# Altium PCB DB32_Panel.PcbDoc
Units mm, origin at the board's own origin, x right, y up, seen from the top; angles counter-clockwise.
Board outline 256.4 x 198.8 mm, 8 copper layers (Top Layer, MidLayer1, MidLayer2, GND-Layer5, MidLayer3, 3V3, MidLayer4, Bottom Layer), stack 1.318 mm thick; 0 components, 444 nets, 12 pads, 0 vias.
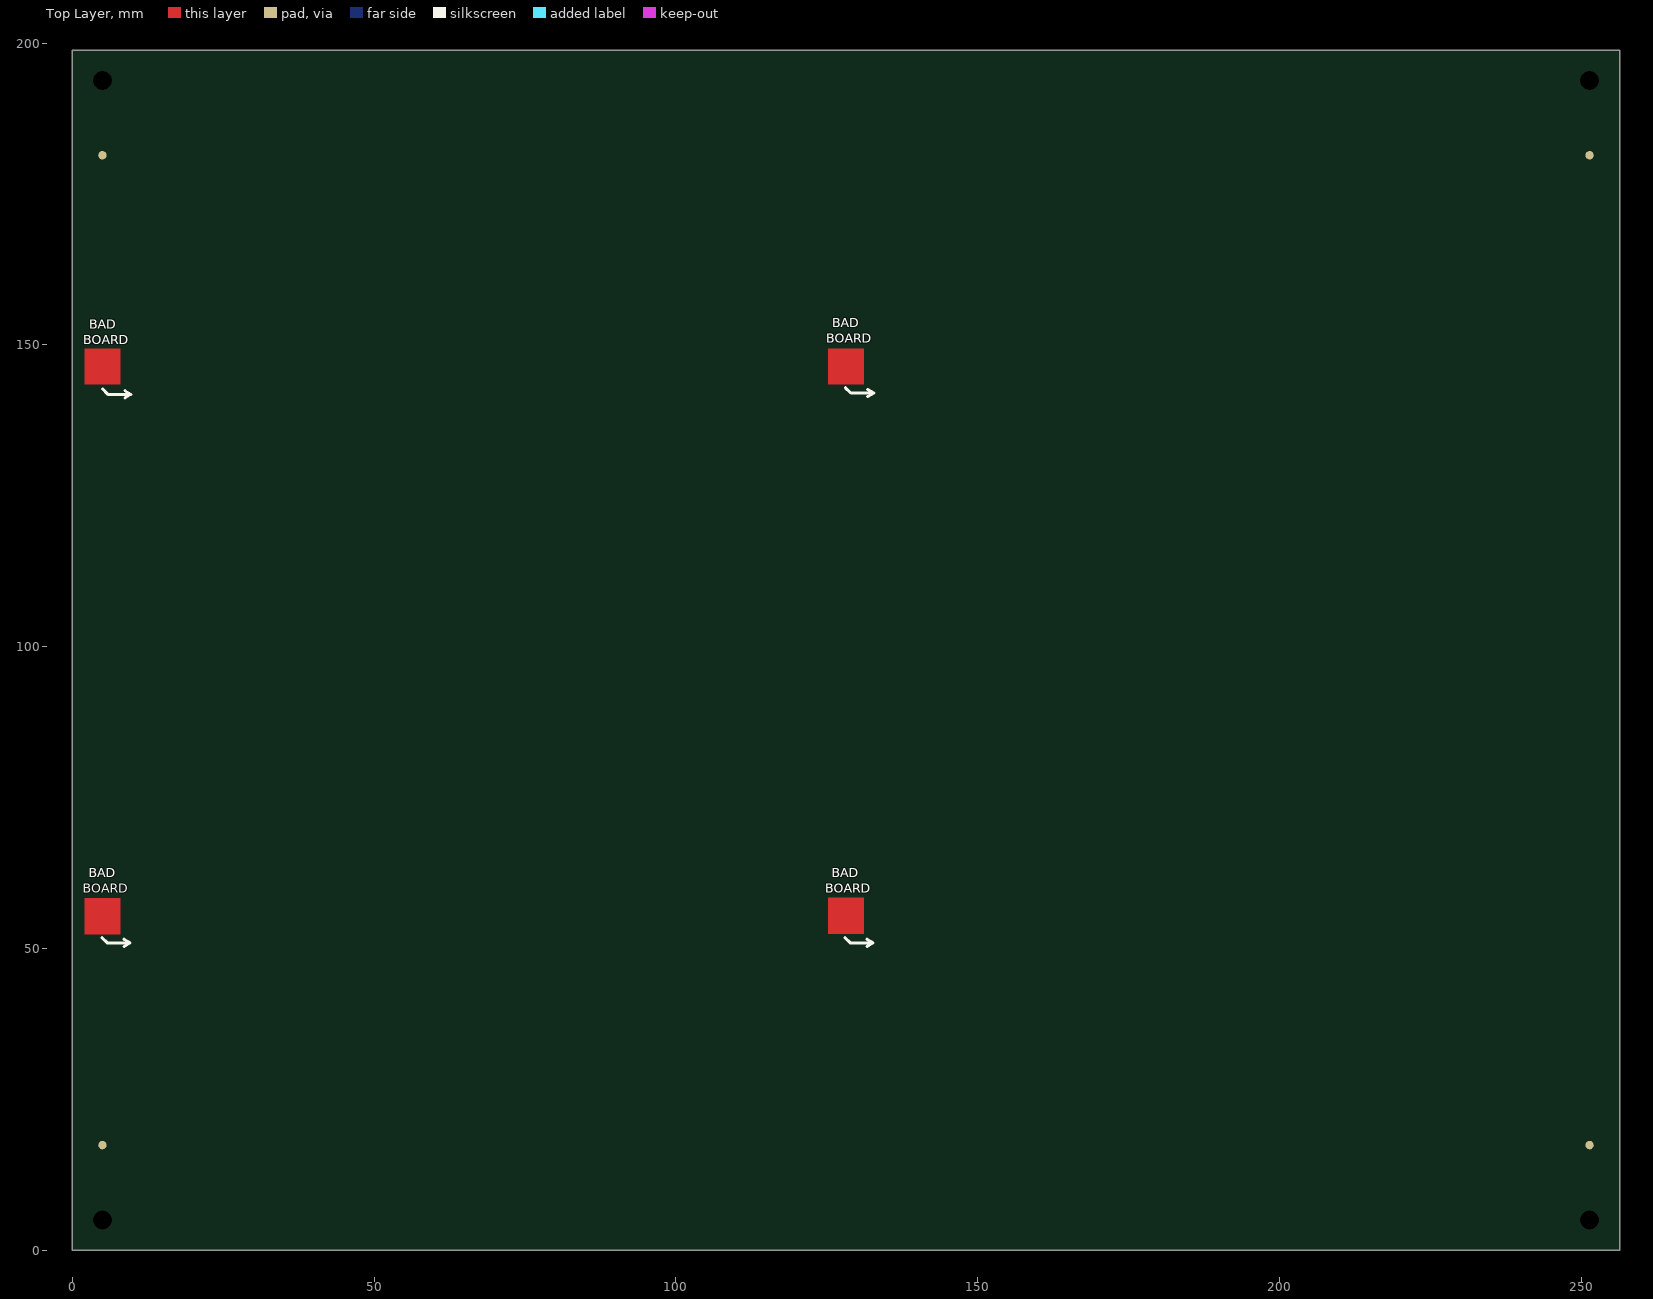
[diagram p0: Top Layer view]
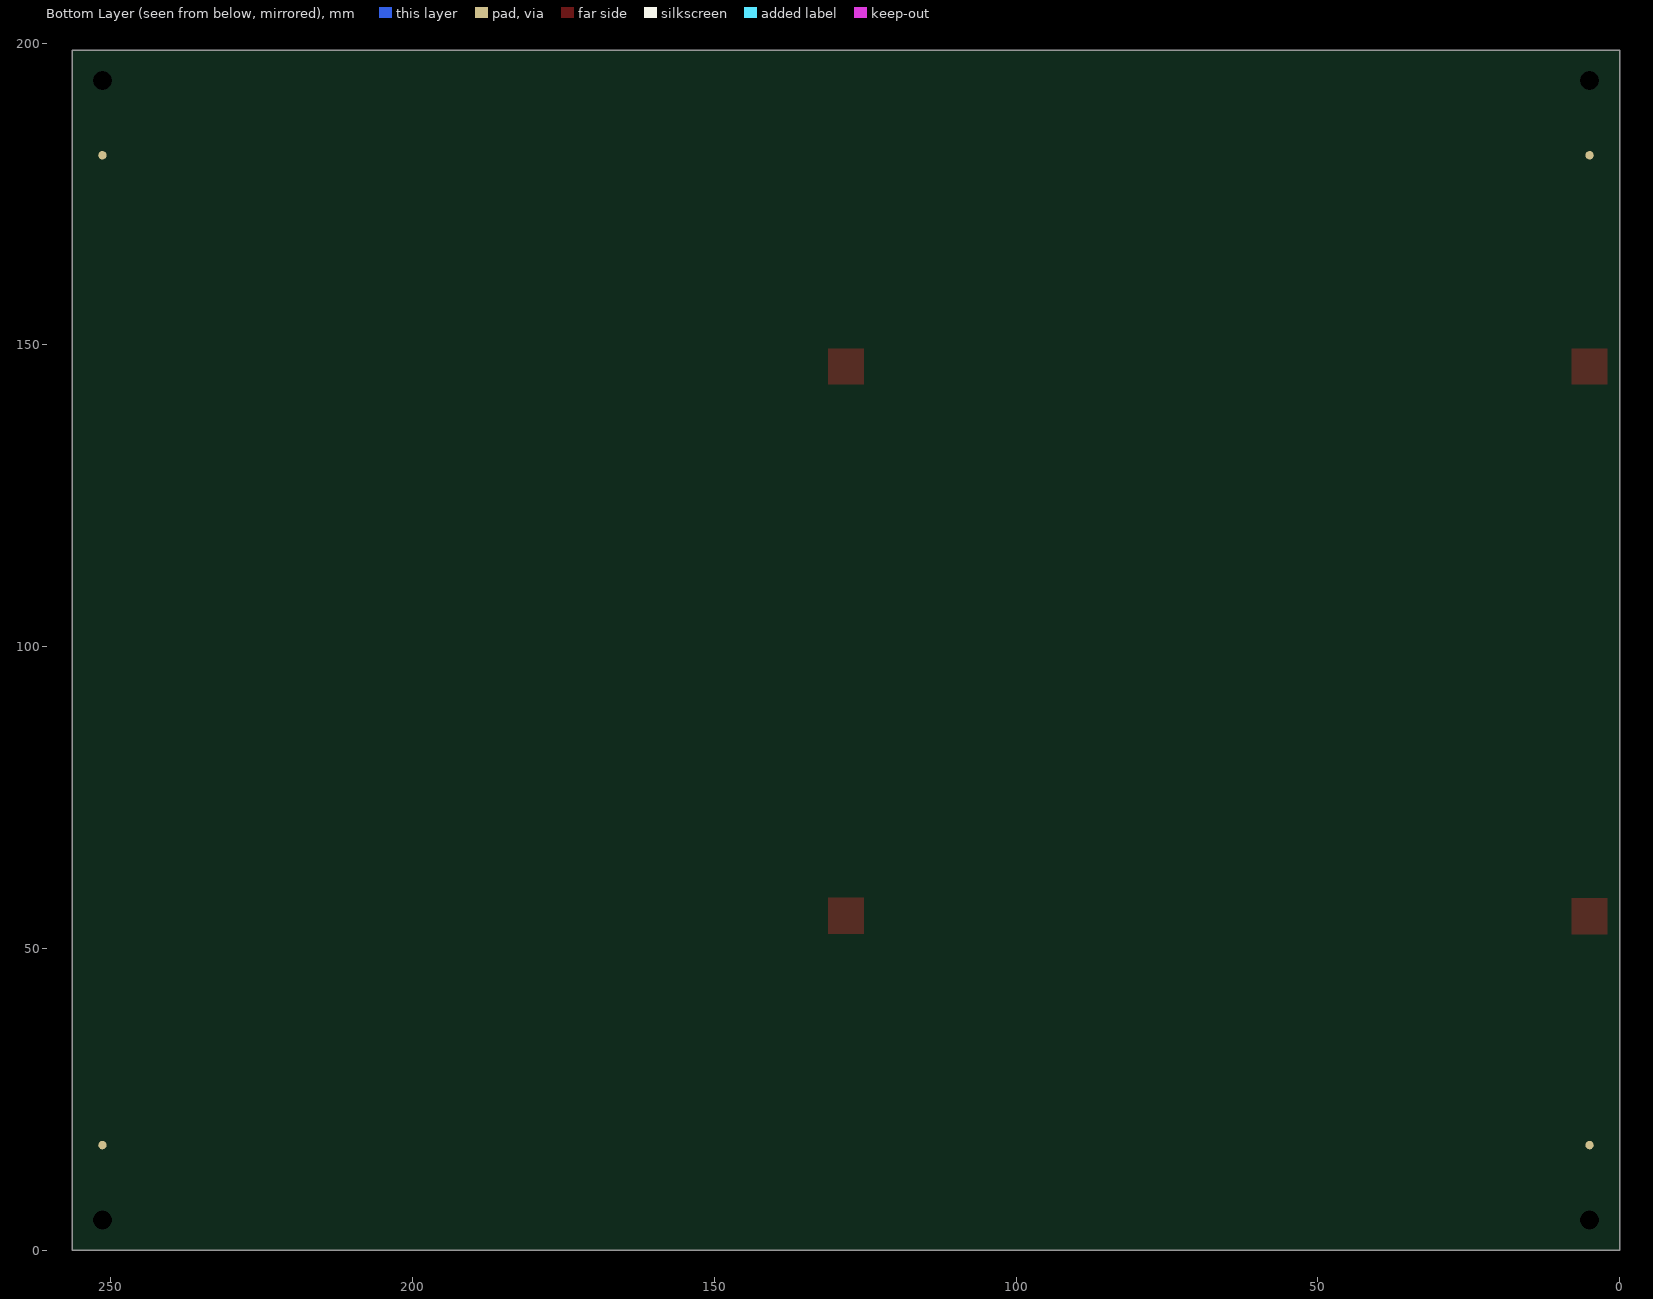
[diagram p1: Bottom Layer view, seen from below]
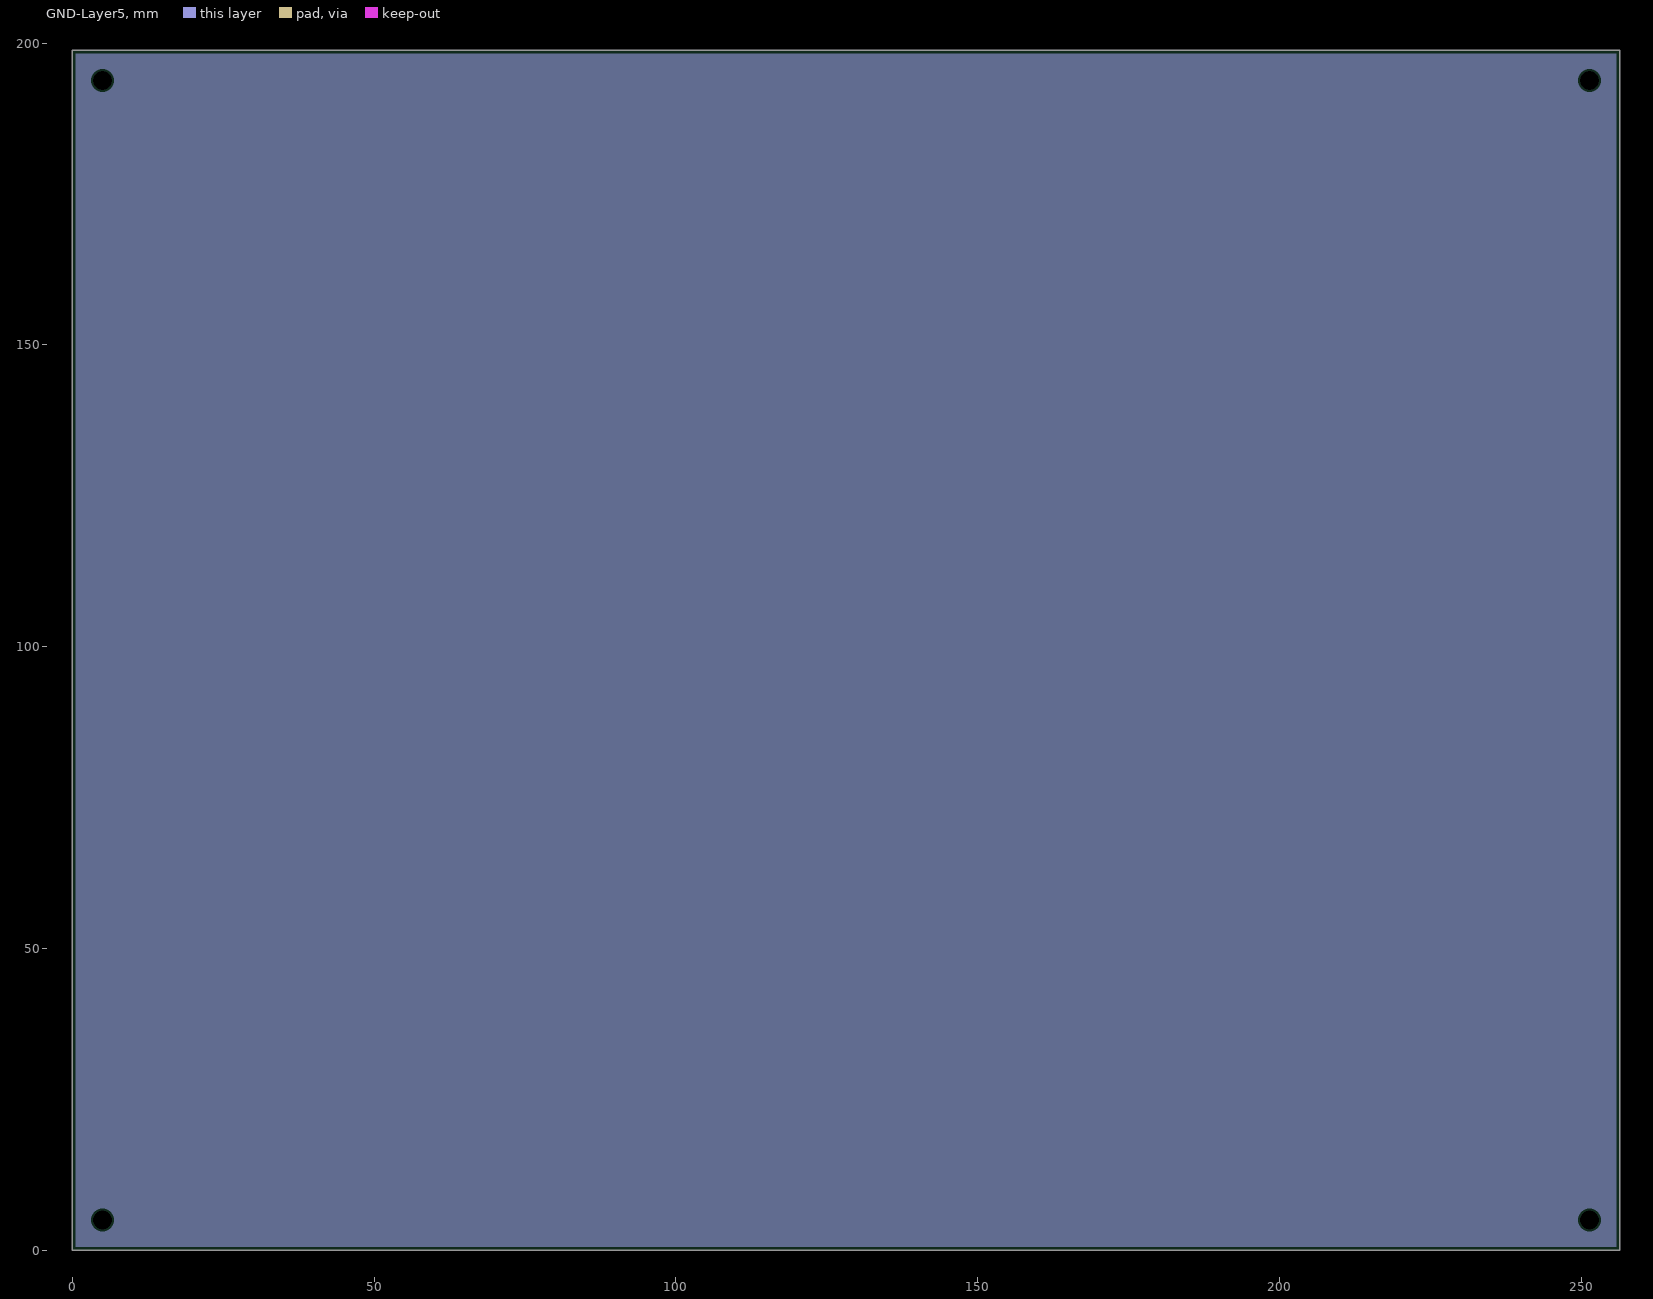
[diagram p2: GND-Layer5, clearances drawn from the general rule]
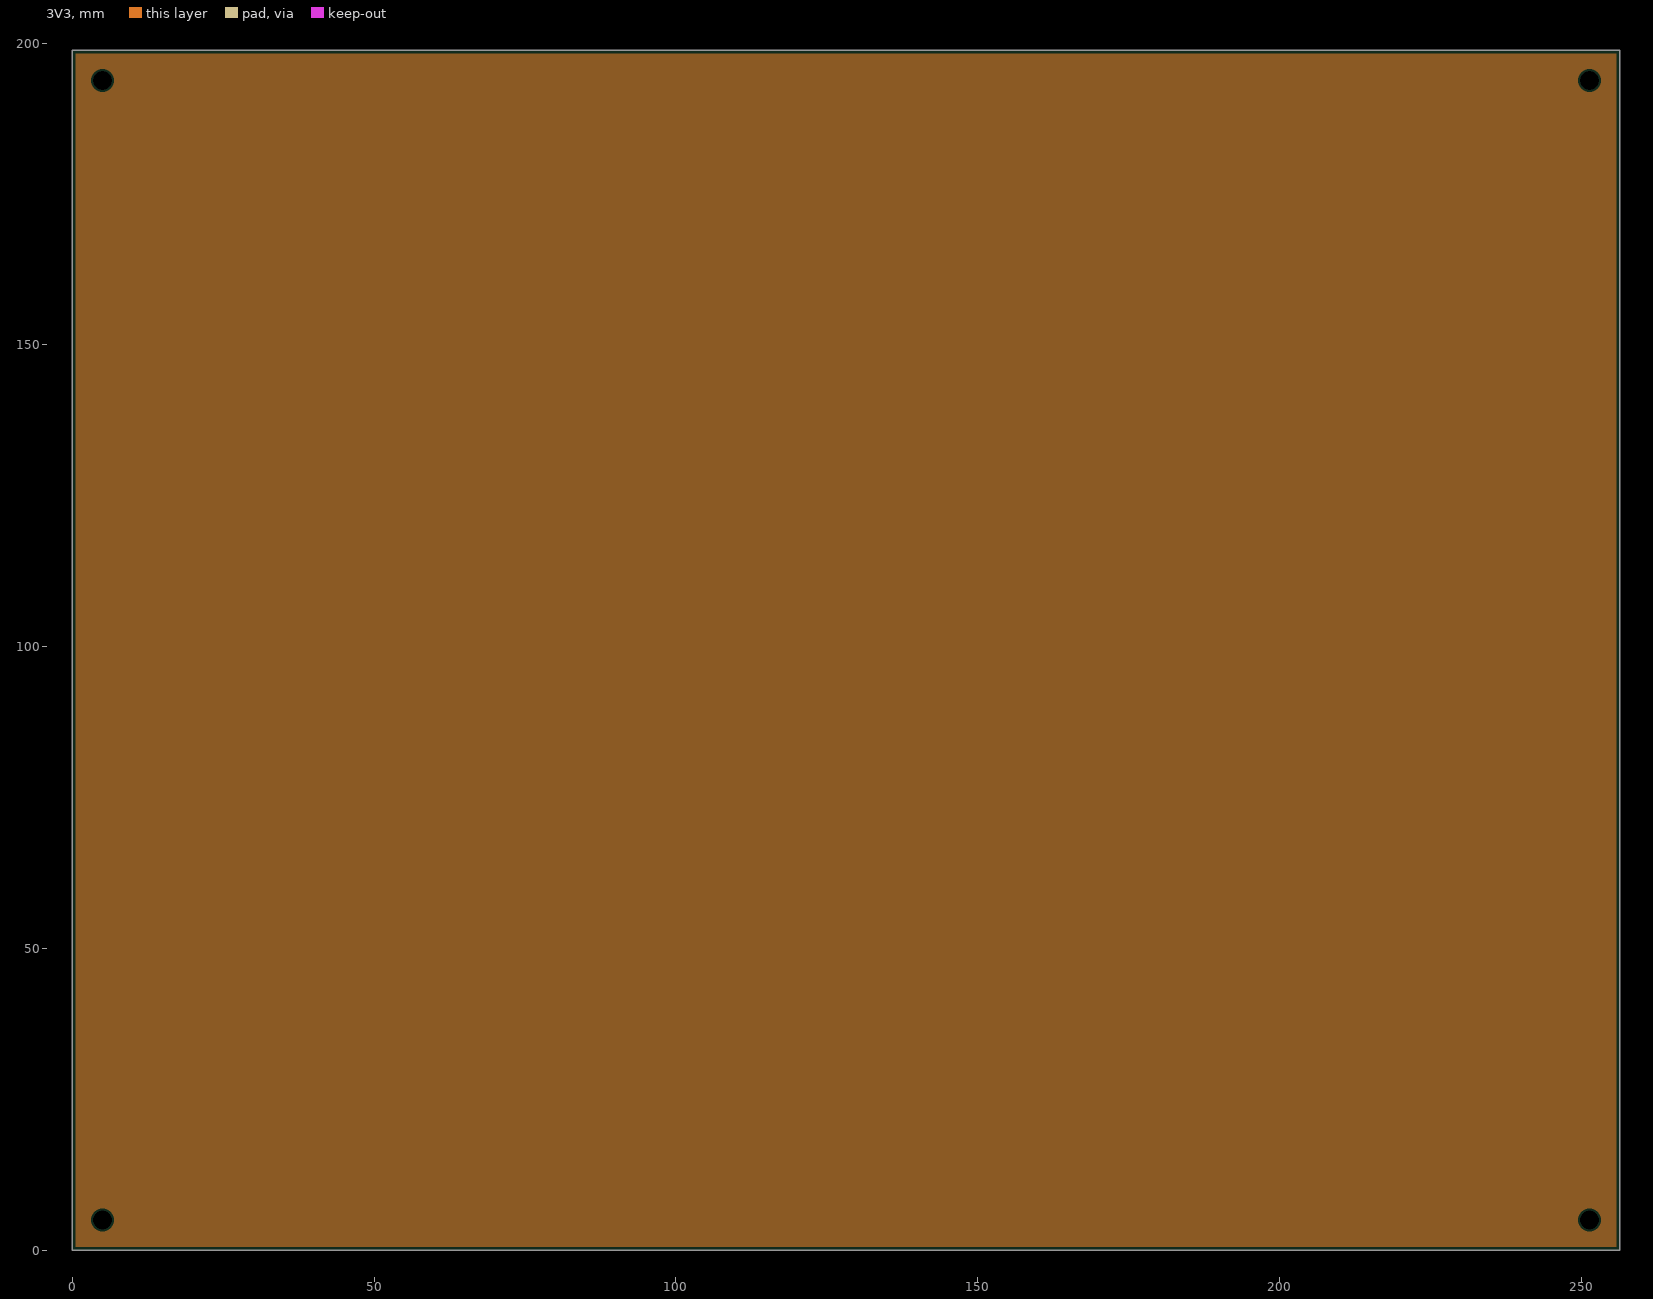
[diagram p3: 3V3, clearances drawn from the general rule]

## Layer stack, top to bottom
Top Layer: signal copper 0.043
Dielectric: prepreg 0.076, FR-4, Dk 4.3
MidLayer1: signal copper 0.0356
Dielectric: core 0.229, FR-4, Dk 4.8
MidLayer2: signal copper 0.0356
Dielectric: prepreg 0.102, FR-4, Dk 4.3
GND-Layer5: plane copper 0.036, net GND
Dielectric: core 0.178, FR-4, Dk 4.8
MidLayer3: signal copper 0.0356
Dielectric: prepreg 0.102, FR-4, Dk 4.8
3V3: plane copper 0.036, net 3V3
Dielectric: core 0.229, FR-4, Dk 4.8
MidLayer4: signal copper 0.0356
Dielectric: prepreg 0.102, FR-4, Dk 4.8
Bottom Layer: signal copper 0.043

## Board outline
0,0 0,198.8 256.3,198.8 256.4,198.8 256.4,0

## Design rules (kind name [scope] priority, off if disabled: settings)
Clearance Clearance_Poly_Tight [InNamedPolygon('FPGAPWR-TL-1V2') Or InNamedPolygon('FPGAPWR-BL-1V2') Or InNamedPolygon('FPGAPWR-BL-3V3') Or InNamedPolygon('FPGAPWR-BL-2V5A') Or InNamedPolygon('FPGAPWR-BL-2V5B') Or InNamedPolygon('FPGAPWR-BL-2V5C') Or InNamedPolygon('FPGAPWR-BL-2V5D') Or InNamedPolygon('FPGAPWR-ML1-1V2') Or InNamedPolygon('FPGAPWR-BL-2V5E') Or InNamedPolygon('FPGAPWR-BL-3V3' )] p1: gap=0.127
Clearance Clearance_Polygon [InPolygon] p2: gap=0.2
Clearance "Pad-Pad Clearance Same Net" [IsPad vs IsPad] p3: gap=0.127
Clearance "Via-Pad Clearance" [IsVia vs IsPad] p4: gap=0.1
Clearance "General Clearance" [All] p5: gap=0.127
ComponentClearance [All] p1 off: gap=0.2 collisioncheckmode=3 verticalgap=0.254 showdistances=FALSE
DiffPairsRouting [All] p1: maxlimit=0.127 minlimit=0.127 mostfreqgap=0.127 maxuncoupledlength=5.08
FabricationTestPointUsage TestPointUsage [All] p1 off: valid=0 allowmultiple=FALSE
FabricationTestpoint Testpoint [All] p1 off: side=3 testpointundercomponent=TRUE minsize=1.016 maxsize=2.54 preferedsize=1.524 minholesize=0 maxholesize=1.016 preferedholesize=0.813 testpointgrid=0.025 allowsidetop=TRUE allowsidebottom=TRUE usegrid=TRUE gridtolerance=0
HoleSize [All] p1: absolutevalues=TRUE maxlimit=5.2 minlimit=0.2 maxpercent=80.000 minpercent=20.000
MatchedLengths DiffPair_MatchedLengths [(IsDifferentialPair And (Name = 'DIFF_RX1'))] p1: tolerance=25.4 checknetsindiffpair=TRUE checkdiffpairvsdiffpair=TRUE checkothers=TRUE
MinimumAnnularRing MinimumAnnularRing_NonPlated [(ObjectKind = 'Pad') And (HoleDiameter >= '0.7') And (PadIsPlated = 'False')] p1: minimumring=-5
MinimumAnnularRing [All] p2: minimumring=0.15
PlaneClearance [All] p1: clearance=0.3
PlaneConnect [All] p1: planeconnectstyle=Direct reliefexpansion=0.5 reliefentries=4 reliefconductorwidth=0.25 reliefairgap=0.25
PolygonConnect PolygonConnect_Via [IsVia] p1: connectstyle=Direct reliefconductorwidth=0.254 reliefentries=4 polygonreliefangle="90 Angle"
PolygonConnect "PolygonConnect - Heatsink" [(HasFootprint('TO-263') AND InNet('VCCINT'))] p2: connectstyle=Direct reliefconductorwidth=0.254 reliefentries=4 polygonreliefangle="90 Angle"
PolygonConnect [All] p3: connectstyle=Relief reliefconductorwidth=0.3 reliefentries=4 polygonreliefangle="90 Angle"
RoutingLayers [All] p1: top layer_v5=FALSE mid layer 1_v5=FALSE mid layer 2_v5=FALSE mid layer 3_v5=FALSE mid layer 4_v5=FALSE bottom layer_v5=FALSE
RoutingVias [All] p1: holewidth=0.3 width=0.6 viastyle="Through Hole" minholewidth=0.3 minwidth=0.6 maxholewidth=0.5 maxwidth=0.9
ShortCircuit ShortCircuit_1 [Net = 'No Net' vs Net = 'No Net'] p1: allowed=TRUE
ShortCircuit [All] p2: allowed=FALSE
SilkscreenOverComponentPads [All] p1: minsilkscreentomaskgap=0.254
SolderMaskExpansion SolderMaskExpansion_Vias [IsVia] p1: expansion=-0.65
SolderMaskExpansion [All] p2: expansion=0.1
Width [All] p1: maxlimit=2.5 minlimit=0.127 preferedwidth=0.127
18 further rules are at their usual default settings.

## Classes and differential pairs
component class MOUNTS-PCB: MH1 MH2 MH3
component class DaughterBoard_FPGA: MH1 MH2 MH3
net class PLL: VCCA_PLL1 VCCA_PLL2 VCCA_PLL3 VCCA_PLL4
net class FPGACONF: CONF_DONE DATA0 DCLK FPGA_CCLK FPGA_DIN FPGA_DONE FPGA_INIT FPGA_M0 FPGA_M1 FPGA_PROGRAM FPGA_TCK FPGA_TDI FPGA_TDO FPGA_TMS MSEL0 MSEL1 NCONFIG NSTATUS TCK TDI TDO TMS
component class U_Bypass_1V2: C1_FP C2_FP C3_FP C4_FP C5_FP C6_FP C7_FP C8_FP C9_FP C10_FP C11_FP C12_FP C13_FP C14_FP C15_FP C16_FP C17_FP C18_FP C19_FP C20_FP C21_FP C22_FP C23_FP C24_FP C25_FP C26_FP C27_FP C28_FP C29_FP C30_FP C31_FP
component class COMP_PLL: C1_PL C2_PL C3_PL C4_PL C5_PL C6_PL C7_PL C8_PL C9_PL C10_PL C11_PL C12_PL C13_PL C14_PL C15_PL C16_PL L2 L3 L4 L5
component class COMP_1V2: C15 C17 C18 C19 C20 C21 C22 L1_PS NT1 NT7 R13 R17
component class U_FPGA_Power: C1_PL C2_PL C3_PL C4_PL C5_PL C6_PL C7_PL C8_PL C9_PL C10_PL C11_PL C12_PL C13_PL C14_PL C15_PL C16_PL L2 L3 L4 L5
net class PWRNET: 1V2 3V3 5V0 AGND GND
differential pair class DIFF_OUT: DIFF_TX0 DIFF_TX1 DIFF_TX2 DIFF_TX3
differential pair class DIFF_IN: DIFF_RX0 DIFF_RX1 DIFF_RX2 DIFF_RX3
net class SW[4..0]: SW0 SW1 SW2 SW3 SW4
net class SRAM_NBE[3..0]: SRAM_NBE0 SRAM_NBE1 SRAM_NBE2 SRAM_NBE3
net class SRAM_D[31..0]: SRAM_D0 SRAM_D1 SRAM_D2 SRAM_D3 SRAM_D4 SRAM_D5 SRAM_D6 SRAM_D7 SRAM_D8 SRAM_D9 SRAM_D10 SRAM_D11 SRAM_D12 SRAM_D13 SRAM_D14 SRAM_D15 SRAM_D16 SRAM_D17 SRAM_D18 SRAM_D19 SRAM_D20 SRAM_D21 SRAM_D22 SRAM_D23 SRAM_D24 SRAM_D25 SRAM_D26 SRAM_D27 SRAM_D28 SRAM_D29 SRAM_D30 SRAM_D31
net class LED[7..0]: LED0 LED1 LED2 LED3 LED4 LED5 LED6 LED7
net class IO[35..0]: IO0 IO1 IO2 IO3 IO4 IO5 IO6 IO7 IO8 IO9 IO10 IO11 IO12 IO13 IO14 IO15 IO16 IO17 IO18 IO19 IO20 IO21 IO22 IO23 IO24 IO25 IO26 IO27 IO28 IO29 IO30 IO31 IO32 IO33 IO34 IO35
net class FPGA_M[2..0]: FPGA_M0 FPGA_M1 FPGA_M2
net class FPGA_ID[3..0]: FPGA_ID0 FPGA_ID1 FPGA_ID2 FPGA_ID3
net class DIP[7..0]: DIP0 DIP1 DIP2 DIP3 DIP4 DIP5 DIP6 DIP7
net class BUS_NBE[3..0]: BUS_NBE0 BUS_NBE1 BUS_NBE2 BUS_NBE3
net class BUS_D[31..0]: BUS_D0 BUS_D1 BUS_D2 BUS_D3 BUS_D4 BUS_D5 BUS_D6 BUS_D7 BUS_D8 BUS_D9 BUS_D10 BUS_D11 BUS_D12 BUS_D13 BUS_D14 BUS_D15 BUS_D16 BUS_D17 BUS_D18 BUS_D19 BUS_D20 BUS_D21 BUS_D22 BUS_D23 BUS_D24 BUS_D25 BUS_D26 BUS_D27 BUS_D28 BUS_D29 BUS_D30 BUS_D31
component class U_SPARTAN3: NT2 NT3 NT4 NT5 NT6 NT8 R1 R2 R3 R4 R7 R8 R12 R14 R18 R20 R22 R23 R24 R25 R26 R27 U1
component class U_LEDS: C98 LED1 LED2 R19 R21 U9
component class U_MotherBoardConnectors: HDR_B HDR_L HDR_T NT1
component class U_SRAM_Free: C1_M C2_M C2B C3_M C4_M C4B C5_M C5B C6_M C7_M C7B C8_M C8B C9_M C9B C10_M C10B C12_M C12B U7B U8B U18 U20
component class U_Bypass_3V3: C38_FP C39_FP C40_FP C41_FP C42_FP C43_FP C44_FP C45_FP C46_FP C47_FP C48_FP C49_FP C50_FP C51_FP C52_FP C53_FP C54_FP C55_FP C56_FP C57_FP C58_FP C59_FP C60_FP C61_FP C62_FP C63_FP C64_FP C65_FP C66_FP C67_FP C68_FP C69_FP C70_FP C71_FP C72_FP C73_FP C74_FP C75_FP C76_FP C77_FP C78_FP C79_FP C80_FP C81_FP C82_FP C83_FP C84_FP C85_FP C86_FP C87_FP C88_FP C89_FP C90_FP C91_FP C92_FP C93_FP C94_FP C95_FP C96_FP C97_FP C98_FP C99_FP C100_FP C101_FP C102_FP C103_FP C104_FP C105_FP C106_FP
component class U_Bypass_Board: C1_MB C1_PSU C2_MB C3_MB C4_MB C6_MB
component class U_FLASH: C1_CM C2_CM C3_CM C4_CM C5_CM C6_CM U1_CM
component class U_SDRAM: C7_CM C8_CM C9_CM C10_CM C11_CM C12_CM C13_CM C14_CM U2_CM U3_CM
component class U_SRAM_Common: C15_CM C16_CM C17_CM C18_CM C19_CM C20_CM C21_CM C22_CM U4_CM U5_CM
net class BUS_A[24..1]: BUS_A1 BUS_A2 BUS_A3 BUS_A4 BUS_A5 BUS_A6 BUS_A7 BUS_A8 BUS_A9 BUS_A10 BUS_A11 BUS_A12 BUS_A13 BUS_A14 BUS_A15 BUS_A16 BUS_A17 BUS_A18 BUS_A19 BUS_A20 BUS_A21 BUS_A22 BUS_A23 BUS_A24
net class DAU_TFT_BLUE[4..0]: DAU_TFT_BLUE0 DAU_TFT_BLUE1 DAU_TFT_BLUE2 DAU_TFT_BLUE3 DAU_TFT_BLUE4
net class DAU_TFT_CL[3..1]: DAU_TFT_CL1 DAU_TFT_CL2 DAU_TFT_CL3
net class DAU_TFT_GREEN[5..0]: DAU_TFT_GREEN0 DAU_TFT_GREEN1 DAU_TFT_GREEN2 DAU_TFT_GREEN3 DAU_TFT_GREEN4 DAU_TFT_GREEN5
net class DAU_TFT_RED[4..0]: DAU_TFT_RED0 DAU_TFT_RED1 DAU_TFT_RED2 DAU_TFT_RED3 DAU_TFT_RED4
net class EXTEND_A[49..0]: EXTEND_A0 EXTEND_A1 EXTEND_A2 EXTEND_A3 EXTEND_A4 EXTEND_A5 EXTEND_A6 EXTEND_A7 EXTEND_A8 EXTEND_A9 EXTEND_A10 EXTEND_A11 EXTEND_A12 EXTEND_A13 EXTEND_A14 EXTEND_A15 EXTEND_A16 EXTEND_A17 EXTEND_A18 EXTEND_A19 EXTEND_A20 EXTEND_A21 EXTEND_A22 EXTEND_A23 EXTEND_A24 EXTEND_A25 EXTEND_A26 EXTEND_A27 EXTEND_A28 EXTEND_A29 EXTEND_A30 EXTEND_A31 EXTEND_A32 EXTEND_A33 EXTEND_A34 EXTEND_A35 EXTEND_A36 EXTEND_A37 EXTEND_A38 EXTEND_A39 EXTEND_A40 EXTEND_A41 EXTEND_A42 EXTEND_A43 EXTEND_A44 EXTEND_A45 EXTEND_A46 EXTEND_A47 EXTEND_A48 EXTEND_A49
net class EXTEND_B[49..0]: EXTEND_B0 EXTEND_B1 EXTEND_B2 EXTEND_B3 EXTEND_B4 EXTEND_B5 EXTEND_B6 EXTEND_B7 EXTEND_B8 EXTEND_B9 EXTEND_B10 EXTEND_B11 EXTEND_B12 EXTEND_B13 EXTEND_B14 EXTEND_B15 EXTEND_B16 EXTEND_B17 EXTEND_B18 EXTEND_B19 EXTEND_B20 EXTEND_B21 EXTEND_B22 EXTEND_B23 EXTEND_B24 EXTEND_B25 EXTEND_B26 EXTEND_B27 EXTEND_B28 EXTEND_B29 EXTEND_B30 EXTEND_B31 EXTEND_B32 EXTEND_B33 EXTEND_B34 EXTEND_B35 EXTEND_B36 EXTEND_B37 EXTEND_B38 EXTEND_B39 EXTEND_B40 EXTEND_B41 EXTEND_B42 EXTEND_B43 EXTEND_B44 EXTEND_B45 EXTEND_B46 EXTEND_B47 EXTEND_B48 EXTEND_B49
net class EXTEND_C[49..0]: EXTEND_C0 EXTEND_C1 EXTEND_C2 EXTEND_C3 EXTEND_C4 EXTEND_C5 EXTEND_C6 EXTEND_C7 EXTEND_C8 EXTEND_C9 EXTEND_C10 EXTEND_C11 EXTEND_C12 EXTEND_C13 EXTEND_C14 EXTEND_C15 EXTEND_C16 EXTEND_C17 EXTEND_C18 EXTEND_C19 EXTEND_C20 EXTEND_C21 EXTEND_C22 EXTEND_C23 EXTEND_C24 EXTEND_C25 EXTEND_C26 EXTEND_C27 EXTEND_C28 EXTEND_C29 EXTEND_C30 EXTEND_C31 EXTEND_C32 EXTEND_C33 EXTEND_C34 EXTEND_C35 EXTEND_C36 EXTEND_C37 EXTEND_C38 EXTEND_C39 EXTEND_C40 EXTEND_C41 EXTEND_C42 EXTEND_C43 EXTEND_C44 EXTEND_C45 EXTEND_C46 EXTEND_C47 EXTEND_C48 EXTEND_C49
net class SRAM_A[20..0]: SRAM_A0 SRAM_A1 SRAM_A2 SRAM_A3 SRAM_A4 SRAM_A5 SRAM_A6 SRAM_A7 SRAM_A8 SRAM_A9 SRAM_A10 SRAM_A11 SRAM_A12 SRAM_A13 SRAM_A14 SRAM_A15 SRAM_A16 SRAM_A17 SRAM_A18
component class U_Memory_CommonBus: C23_CM C24_CM
component class U_PSU_MAX1831_1V2: C15 C16 C17 C18 C19 C20 C21 C22 L1_PS R11 R13 R15 R16 R17 TP7 TP8 U2
component class U_PSU: NT7 R5 R6 TP1 TP2 TP3 TP4

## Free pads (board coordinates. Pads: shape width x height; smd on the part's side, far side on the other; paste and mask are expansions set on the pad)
  round 2.692 hole 3.2 unplated mask+0.889: 126N(5,5) 126N(5,193.8) 126N(251.4,5) 126N(251.4,193.8)
  round 1.397 smd far side paste-2.54 mask+1.321: fidbot(5,17.4) fidbot(5,181.4) fidbot(251.4,17.4) fidbot(251.4,181.4)
  round 1.397 smd paste-2.54 mask+1.321: fidtop(5,17.4) fidtop(5,181.4) fidtop(251.4,17.4) fidtop(251.4,181.4)

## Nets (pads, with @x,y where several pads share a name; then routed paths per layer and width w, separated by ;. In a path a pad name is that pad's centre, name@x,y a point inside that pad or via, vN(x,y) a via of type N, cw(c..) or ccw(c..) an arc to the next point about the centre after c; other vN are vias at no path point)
1V2: 
3V3: 
5V0: 
AGND: 
BUS_A1: 
BUS_A2: 
BUS_A3: 
BUS_A4: 
BUS_A5: 
BUS_A6: 
BUS_A7: 
BUS_A8: 
BUS_A9: 
BUS_A10: 
BUS_A11: 
BUS_A12: 
BUS_A13: 
BUS_A14: 
BUS_A15: 
BUS_A16: 
BUS_A17: 
BUS_A18: 
BUS_A19: 
BUS_A20: 
BUS_A21: 
BUS_A22: 
BUS_A23: 
BUS_A24: 
BUS_D0: 
BUS_D1: 
BUS_D2: 
BUS_D3: 
BUS_D4: 
BUS_D5: 
BUS_D6: 
BUS_D7: 
BUS_D8: 
BUS_D9: 
BUS_D10: 
BUS_D11: 
BUS_D12: 
BUS_D13: 
BUS_D14: 
BUS_D15: 
BUS_D16: 
BUS_D17: 
BUS_D18: 
BUS_D19: 
BUS_D20: 
BUS_D21: 
BUS_D22: 
BUS_D23: 
BUS_D24: 
BUS_D25: 
BUS_D26: 
BUS_D27: 
BUS_D28: 
BUS_D29: 
BUS_D30: 
BUS_D31: 
BUS_FLASH_NBUSY: 
BUS_FLASH_NCS: 
BUS_FLASH_NRESET: 
BUS_NBE0: 
BUS_NBE1: 
BUS_NBE2: 
BUS_NBE3: 
BUS_NOE: 
BUS_NWE: 
BUS_RAM_NCS: 
BUS_SDRAM_CKE: 
BUS_SDRAM_CLK: 
BUS_SDRAM_NCAS: 
BUS_SDRAM_NCS: 
BUS_SDRAM_NRAS: 
BUZZER: 
CAN_RXD: 
CAN_TXD: 
COMP: 
CONF_DONE: 
DATA0: 
DAU_RESET_SW: 
DAU_SPARE: 
DAU_TFT_BLIGHT: 
DAU_TFT_BLUE0: 
DAU_TFT_BLUE1: 
DAU_TFT_BLUE2: 
DAU_TFT_BLUE3: 
DAU_TFT_BLUE4: 
DAU_TFT_CL1: 
DAU_TFT_CL2: 
DAU_TFT_CL3: 
DAU_TFT_DISP_ON: 
DAU_TFT_GREEN0: 
DAU_TFT_GREEN1: 
DAU_TFT_GREEN2: 
DAU_TFT_GREEN3: 
DAU_TFT_GREEN4: 
DAU_TFT_GREEN5: 
DAU_TFT_IRQ: 
DAU_TFT_M: 
DAU_TFT_MUX: 
DAU_TFT_POL: 
DAU_TFT_RED0: 
DAU_TFT_RED1: 
DAU_TFT_RED2: 
DAU_TFT_RED3: 
DAU_TFT_RED4: 
DAU_TFT_STH: 
DAU_TFT_STV: 
DCLK: 
DIP0: 
DIP1: 
DIP2: 
DIP3: 
DIP4: 
DIP5: 
DIP6: 
DIP7: 
EXTEND_A0: 
EXTEND_A1: 
EXTEND_A2: 
EXTEND_A3: 
EXTEND_A4: 
EXTEND_A5: 
EXTEND_A6: 
EXTEND_A7: 
EXTEND_A8: 
EXTEND_A9: 
EXTEND_A10: 
EXTEND_A11: 
EXTEND_A12: 
EXTEND_A13: 
EXTEND_A14: 
EXTEND_A15: 
EXTEND_A16: 
EXTEND_A17: 
EXTEND_A18: 
EXTEND_A19: 
EXTEND_A20: 
EXTEND_A21: 
EXTEND_A22: 
EXTEND_A23: 
EXTEND_A24: 
EXTEND_A25: 
EXTEND_A26: 
EXTEND_A27: 
EXTEND_A28: 
EXTEND_A29: 
EXTEND_A30: 
EXTEND_A31: 
EXTEND_A32: 
EXTEND_A33: 
EXTEND_A34: 
EXTEND_A35: 
EXTEND_A36: 
EXTEND_A37: 
EXTEND_A38: 
EXTEND_A39: 
EXTEND_A40: 
EXTEND_A41: 
EXTEND_A42: 
EXTEND_A43: 
EXTEND_A44: 
EXTEND_A45: 
EXTEND_A46: 
EXTEND_A47: 
EXTEND_A48: 
EXTEND_A49: 
EXTEND_B0: 
EXTEND_B1: 
EXTEND_B2: 
EXTEND_B3: 
EXTEND_B4: 
EXTEND_B5: 
EXTEND_B6: 
EXTEND_B7: 
EXTEND_B8: 
EXTEND_B9: 
EXTEND_B10: 
EXTEND_B11: 
EXTEND_B12: 
EXTEND_B13: 
EXTEND_B14: 
EXTEND_B15: 
EXTEND_B16: 
EXTEND_B17: 
EXTEND_B18: 
EXTEND_B19: 
EXTEND_B20: 
EXTEND_B21: 
EXTEND_B22: 
EXTEND_B23: 
EXTEND_B24: 
EXTEND_B25: 
EXTEND_B26: 
EXTEND_B27: 
EXTEND_B28: 
EXTEND_B29: 
EXTEND_B30: 
EXTEND_B31: 
EXTEND_B32: 
EXTEND_B33: 
EXTEND_B34: 
EXTEND_B35: 
EXTEND_B36: 
EXTEND_B37: 
EXTEND_B38: 
EXTEND_B39: 
EXTEND_B40: 
EXTEND_B41: 
EXTEND_B42: 
EXTEND_B43: 
EXTEND_B44: 
EXTEND_B45: 
EXTEND_B46: 
EXTEND_B47: 
EXTEND_B48: 
EXTEND_B49: 
EXTEND_C0: 
EXTEND_C1: 
EXTEND_C2: 
EXTEND_C3: 
EXTEND_C4: 
EXTEND_C5: 
EXTEND_C6: 
EXTEND_C7: 
EXTEND_C8: 
EXTEND_C9: 
EXTEND_C10: 
EXTEND_C11: 
EXTEND_C12: 
EXTEND_C13: 
EXTEND_C14: 
EXTEND_C15: 
EXTEND_C16: 
EXTEND_C17: 
EXTEND_C18: 
EXTEND_C19: 
EXTEND_C20: 
EXTEND_C21: 
EXTEND_C22: 
EXTEND_C23: 
EXTEND_C24: 
EXTEND_C25: 
EXTEND_C26: 
EXTEND_C27: 
EXTEND_C28: 
EXTEND_C29: 
EXTEND_C30: 
EXTEND_C31: 
EXTEND_C32: 
EXTEND_C33: 
EXTEND_C34: 
EXTEND_C35: 
EXTEND_C36: 
EXTEND_C37: 
EXTEND_C38: 
EXTEND_C39: 
EXTEND_C40: 
EXTEND_C41: 
EXTEND_C42: 
EXTEND_C43: 
EXTEND_C44: 
EXTEND_C45: 
EXTEND_C46: 
EXTEND_C47: 
EXTEND_C48: 
EXTEND_C49: 
FB: 
FPGA_CCLK: 
FPGA_CLK: 
FPGA_CLK1: 
FPGA_CLK2: 
FPGA_DIN: 
FPGA_DONE: 
FPGA_ID0: 
FPGA_ID1: 
FPGA_ID2: 
FPGA_ID3: 
FPGA_INIT: 
FPGA_INSTALLED: 
FPGA_M0: 
FPGA_M1: 
FPGA_M2: 
FPGA_PROG_CLK: 
FPGA_PROG_PWR_ON: 
FPGA_PROGRAM: 
FPGA_TCK: 
FPGA_TDI: 
FPGA_TDO: 
FPGA_TMS: 
GND: 
IO0: 
IO1: 
IO2: 
IO3: 
IO4: 
IO5: 
IO6: 
IO7: 
IO8: 
IO9: 
IO10: 
IO11: 
IO12: 
IO13: 
IO14: 
IO15: 
IO16: 
IO17: 
IO18: 
IO19: 
IO20: 
IO21: 
IO22: 
IO23: 
IO24: 
IO25: 
IO26: 
IO27: 
IO28: 
IO29: 
IO30: 
IO31: 
IO32: 
IO33: 
IO34: 
IO35: 
KBCLOCK: 
KBDATA: 
LED0: 
LED1: 
LED2: 
LED3: 
LED4: 
LED5: 
LED6: 
LED7: 
LED_PGM: 
LED_PWR: 
LX: 
MOUSECLOCK: 
MOUSEDATA: 
MSEL0: 
MSEL1: 
NCONFIG: 
NetLED2_1: 
NetR15_1: 
NEXUS_TCK: 
NEXUS_TDI: 
NEXUS_TDO: 
NEXUS_TMS: 
NSTATUS: 
REF_1V2: 
REF_CLK: 
RS232_CTS: 
RS232_RTS: 
RS232_RX: 
RS232_TX: 
SCL: 
SDA: 
SDRAM_FEEDBACK: 
SPI_CLK: 
SPI_DIN: 
SPI_DOUT: 
SPI_MODE: 
SPI_SEL: 
SRAM_A0: 
SRAM_A1: 
SRAM_A2: 
SRAM_A3: 
SRAM_A4: 
SRAM_A5: 
SRAM_A6: 
SRAM_A7: 
SRAM_A8: 
SRAM_A9: 
SRAM_A10: 
SRAM_A11: 
SRAM_A12: 
SRAM_A13: 
SRAM_A14: 
SRAM_A15: 
SRAM_A16: 
SRAM_A17: 
SRAM_A18: 
SRAM_D0: 
SRAM_D1: 
SRAM_D2: 
SRAM_D3: 
SRAM_D4: 
SRAM_D5: 
SRAM_D6: 
SRAM_D7: 
SRAM_D8: 
SRAM_D9: 
SRAM_D10: 
SRAM_D11: 
SRAM_D12: 
SRAM_D13: 
SRAM_D14: 
SRAM_D15: 
SRAM_D16: 
SRAM_D17: 
SRAM_D18: 
SRAM_D19: 
SRAM_D20: 
SRAM_D21: 
SRAM_D22: 
SRAM_D23: 
SRAM_D24: 
SRAM_D25: 
SRAM_D26: 
SRAM_D27: 
SRAM_D28: 
SRAM_D29: 
SRAM_D30: 
SRAM_D31: 
SRAM_NBE0: 
SRAM_NBE1: 
SRAM_NBE2: 
SRAM_NBE3: 
SRAM_NCS: 
SRAM_NOE: 
SRAM_NWE: 
STATUS_LED: 
SW0: 
SW1: 
SW2: 
SW3: 
SW4: 
TCK: 
TDI: 
TDO: 
TMS: 
TOFF: 
VCCA_PLL1: 
VCCA_PLL2: 
VCCA_PLL3: 
VCCA_PLL4: 
VCCX: 
VCCX_REF: 
VFILT: 

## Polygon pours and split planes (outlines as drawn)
GND on GND-Layer5 (split plane): 255.89,0.51 0.51,0.51 0.51,198.29 255.89,198.29
3V3 on 3V3 (split plane): 255.89,0.51 0.51,0.51 0.51,198.29 255.89,198.29

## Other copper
Top Layer:
  rectangle: 2,52.3 8,58.3
  rectangle: 125.2,52.4 131.2,58.4
  rectangle: 125.2,143.4 131.2,149.4
  rectangle: 2,143.4 8,149.4
  rectangle: 2,52.3 8,58.3
  rectangle: 125.2,52.4 131.2,58.4
  rectangle: 125.2,143.4 131.2,149.4
  rectangle: 2,143.4 8,149.4

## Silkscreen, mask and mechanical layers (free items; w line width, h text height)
Top Overlay:
  lines w0.508: 5.8,50.9 4.9,51.8 5.8,50.9 ; 5.8,50.9 9.6,50.9 ; 5.8,50.9 9.6,50.9 ; 5.9,141.8 9.7,141.8 ; 5.9,141.8 5,142.7 5.9,141.8 ; 5.9,141.8 9.7,141.8 ; 9.6,50.9 8.6,50.3 9.6,50.9 ; 9.6,50.9 8.6,51.5 9.6,50.9 ; 9.7,141.8 8.7,142.4 9.7,141.8 ; 9.7,141.8 8.7,141.2 9.7,141.8 ; 128.9,50.9 128,51.8 128.9,50.9 ; 128.9,50.9 132.7,50.9 ; 128.9,50.9 132.7,50.9 ; 129,142 128.1,142.9 129,142 ; 129,142 132.8,142 ; 129,142 132.8,142 ; 132.7,50.9 131.7,50.3 132.7,50.9 ; 132.7,50.9 131.7,51.5 132.7,50.9 ; 132.8,142 131.8,141.4 132.8,142 ; 132.8,142 131.8,142.6 132.8,142
  text "BAD" at 125.9,152.9 h1.52
  text "BAD" at 125.9,152.9 h1.52
  text "BAD" at 2.8,152.7 h1.52
  text "BAD" at 2.8,152.7 h1.52
  text "BOARD" at 124.9,150.3 h1.52
  text "BOARD" at 124.9,150.3 h1.52
  text "BOARD" at 1.8,150.1 h1.52
  text "BOARD" at 1.8,150.1 h1.52
  text "BAD" at 2.7,61.8 h1.52
  text "BAD" at 2.7,61.8 h1.52
  text "BAD" at 125.8,61.8 h1.52
  text "BAD" at 125.8,61.8 h1.52
  text "BOARD" at 1.7,59.2 h1.52
  text "BOARD" at 124.8,59.2 h1.52
  text "BOARD" at 124.8,59.2 h1.52
Top Solder:
  rectangle: 2,52.3 8,58.3
  rectangle: 125.2,52.4 131.2,58.4
  rectangle: 125.2,143.4 131.2,149.4
  rectangle: 2,143.4 8,149.4
  rectangle: 2,52.3 8,58.3
  rectangle: 125.2,52.4 131.2,58.4
  rectangle: 125.2,143.4 131.2,149.4
  rectangle: 2,143.4 8,149.4
6. FabNotes:
  drawing of 1029 lines, arcs and shapes, not listed
  text "DAUGHTER-BOARD PANEL" at 328.041,284.962 h1.25
  text "DESIGN INFORMATION" at 271.802,284.943 h1.25
  text "BOARD NAME:" at 309.394,284.943 h1.25
  text "BOARD TECHNOLOGY" at 271.802,282.403 h1.25
  text "BOARD SIZE (REFER ALSO PROFILING INFORMATION)" at 320.062,282.403 h1.25
  text "5.0" at 273.923,280.214 h1.25
  text "256.40" at 322.782,280.129 h1.25
  text "12.0" at 287.601,280.041 h1.25
  text "198.80mm" at 345.782,280.029 h1.25
  text "5.0" at 301.571,279.914 h1.25
  text "X" at 338.731,279.355 h1.25
  text "(MIN. TRACK/   PADS  /   CLEARANCE     IN 0.001'')" at 270.278,277.323 h1.25
  text "RECOMMENDED LAYUP" at 180.945,276.439 h1.25
  text "MINIMUM ANNULAR RING 0.05MM (0.002'') EXTERNAL PER IPC-2221 CLASS 3 LEVEL C AND IS THE" at 271.802,274.783 h1.25
  text "MANUFACTURING REGISTRATION ALLOWANCE" at 271.802,272.497 h1.25
  text "LAND SIZE CALCULATION MINIMUM - NOMINAL HOLE SIZE + 0.508MM (0.020'')" at 271.802,269.703 h1.25
  text "LAYER STACK CONFIGURATION" at 170.271,266.166 h1.25
  text "CIRCUIT TYPE:" at 271.802,265.131 h1.25
  text "SS" at 294.662,265.131 h1.25
  text "DS" at 312.442,265.131 h1.25
  text "X" at 327.047,265.131 h1.25
  text "PTH" at 330.222,265.131 h1.25
  text "ML" at 341.144,265.131 h1.25
  text "X" at 344.954,265.131 h1.25
  text "No. of Layers" at 348.002,265.131 h1.25
  text "8" at 365.363,264.974 h1.25
  text "FINGER CONNECTOR DIM PER:" at 271.802,262.083 h1.25
  text "AS SHOWN" at 348.002,262.083 h1.25
  text "No. OFF TOTAL" at 288.566,259.289 h1.25
  text "ONE SIDE" at 330.222,259.289 h1.25
  text "BOTH SIDES" at 348.002,259.035 h1.25
  text "8 LAYER BUILD" at 181.236,259.003 h1.25
  text "X" at 309.314,256.468 h1.25
  text "VIAS:" at 271.802,256.368 h1.25
  text "NONE" at 283.232,256.368 h1.25
  text "X" at 291.614,256.368 h1.25
  text "FEED THRU'" at 294.662,256.368 h1.25
  text "TENTED" at 312.442,256.368 h1.25
  text "BURIED LAYER SEQUENCE" at 330.222,256.368 h1.25
  text "UNIQUE DRILL" at 294.662,253.32 h1.25
  text "2 SIZE" at 312.442,253.32 h1.25
  text "BLIND LAYER SEQUENCE" at 330.222,253.32 h1.25
  text "Layer Stack Manager (PCB)" at 307.235,251.034 h1.25
  text "X" at 344.954,251.034 h1.25
  text "AS SHOWN" at 348.002,251.034 h1.25
  text "LAYER CONSTRUCTION PER:" at 271.802,250.907 h1.25
  text "-  COPPER CLAD" at 198.262,250.64 h0.75
  text "-  35 Micron H.T.E 1.4mil" at 209.133,250.64 h0.75
  text "TL" at 171.705,250.513 h1.25
  text "TOP LAYER" at 158.974,249.929 h1.25
  text "-  PRE-PREG" at 198.897,249.243 h0.75
  text "-  1080 5mil" at 209.133,249.217 h0.75
  text "Altium Designer 6.6" at 347.841,248.247 h1.25
  text "ARTWORK:" at 271.802,248.113 h1.25
  text "MANUAL" at 294.662,248.113 h1.25
  text "DIGITISED" at 312.442,248.113 h1.25
  text "X" at 327.174,248.113 h1.25
  text "CAD" at 330.222,248.113 h1.25
  text "TYPE" at 341.144,248.113 h1.25
  text "MID LAYER 1" at 158.974,246.92 h1.25
  text "L1" at 171.705,246.831 h1.25
  text "-  35 Micron H.T.E 1.4mil" at 209.133,246.779 h0.75
  text "-  COPPER CLAD" at 198.242,246.776 h0.75
  text "-  CORE" at 198.897,245.435 h0.75
  text "-  10mil" at 209.133,245.433 h0.75
  text "-  35 Micron H.T.E 1.4mil" at 209.133,244.061 h0.75
  text "-  COPPER CLAD" at 198.242,244.046 h0.75
  text "MID LAYER 2" at 158.997,243.86 h1.25
  text "L2" at 171.697,243.86 h1.25
  text "ARTWORK/PATTERN MASTER LIST" at 271.802,243.414 h1.25
  text "-  1080 5mil" at 209.133,242.791 h0.75
  text "-  PRE-PREG" at 198.877,242.752 h0.75
  text "DESCRIPTION" at 273.072,241.001 h1.25
  text "DRAWING No./CAD FILE REF." at 291.741,241.001 h1.25
  text "LAYER NAME" at 333.016,241.001 h1.25
  text "GERBER FILE REF" at 353.768,240.925 h1.25
  text "P1" at 171.697,240.304 h1.25
  text "-  COPPER CLAD" at 198.223,240.285 h0.75
  text "-  35 Micron H.T.E 1.4mil" at 209.133,240.251 h0.75
  text "INTERNAL PLANE 1" at 154.306,240.214 h1.25
  text "-  CORE" at 198.877,238.944 h0.75
  text "-  10mil" at 209.133,238.93 h0.75
  text "PCB FILE" at 271.548,238.461 h1.25
  text "2x2 Peripheral Panel" at 291.907,238.403 h1.25
  text "PcbDoc" at 323.161,238.385 h1.25
  text "-  COPPER CLAD" at 198.223,237.555 h0.75
  text "-  35 Micron H.T.E 1.4mil" at 209.133,237.533 h0.75
  text "MID LAYER 3" at 158.466,237.196 h1.25
  text "L3" at 171.547,237.196 h1.25
  text "-  1080 5mil" at 209.133,236.263 h0.75
  text "-  PRE-PREG" at 198.858,236.261 h0.75
  text "Top Paste Mask" at 331.34,235.921 h1.25
  text "GTP" at 324.341,235.871 h1.25
  text "GTP" at 373.961,235.845 h1.25
  text "GERBER FILE" at 271.548,235.794 h1.25
  text "INTERNAL PLANE 2" at 153.64,234.021 h1.25
  text "P2" at 171.42,234.021 h1.25
  text "-  35 Micron H.T.E 1.4mil" at 209.133,233.8 h0.75
  text "-  COPPER CLAD" at 198.204,233.794 h0.75
  text "GTO" at 324.341,233.371 h1.25
  text "GTO" at 373.91,233.356 h1.25
  text "Top Overlay" at 331.34,233.33 h1.25
  text "GERBER FILE" at 271.548,233.254 h1.25
  text "-  10mil" at 209.133,232.453 h0.75
  text "-  CORE" at 198.858,232.453 h0.75
  text "-  COPPER CLAD" at 198.204,231.064 h0.75
  text "-  35 Micron H.T.E 1.4mil" at 209.133,231.056 h0.75
  text "MID LAYER 4" at 158.959,230.878 h1.25
  text "L4" at 171.659,230.878 h1.25
  text "Top Solder Mask" at 331.34,230.892 h1.25
  text "GTS" at 324.341,230.871 h1.25
  text "GTS" at 373.961,230.765 h1.25
  text "GERBER FILE" at 271.548,230.714 h1.25
  text "-  PRE-PREG" at 198.839,229.77 h0.75
  text "-  1080 5mil" at 209.133,229.761 h0.75
  text "Board Layer 1" at 353.7,228.4 h1.25
  text "Top Layer" at 331.34,228.301 h1.25
  text "GTL" at 373.961,228.225 h1.25
  text "GERBER FILE" at 271.548,228.174 h1.25
  text "GTL" at 324.341,228.171 h1.25
  text "-  35 Micron H.T.E 1.4mil" at 209.133,227.323 h0.75
  text "BOTTOM LAYER" at 157.006,227.314 h1.25
  text "BL" at 171.659,227.322 h1.25
  text "-  COPPER CLAD" at 198.184,227.303 h0.75
  text "Mid Layer 1" at 331.568,223.242 h1.25
  text "Board Layer 2" at 353.768,223.242 h1.25
  text "G1" at 324.3,223.2 h1.25
  text "G1" at 374,223.2 h1.25
  text "GERBER FILE" at 271.548,223.154 h1.25
  text "G2" at 324.3,220.7 h1.25
  text "G2" at 374,220.7 h1.25
  text "Mid Layer 2" at 331.568,220.642 h1.25
  text "Board Layer 3" at 353.668,220.642 h1.25
  text "GERBER FILE" at 271.548,220.614 h1.25
  text "1.6mm" at 189.046,220.263 h1.25
  text "TOTAL BOARD THICKNESS: APPROX" at 156.506,220.114 h1.25
  text "(61.2mil)" at 195.806,220.114 h1.25
  text "V-GROOVE" at 248,219.9 h1.25 r90
  text "V-GROOVE" at 11.6,218.6 h1.25 r90
  text "GP1" at 324.3,218.2 h1.25
  text "Board Layer 4" at 353.7,218.2 h1.25
  text "GP1" at 374,218.2 h1.25
  text "GND" at 331.268,218.142 h1.25
  text "GERBER FILE" at 271.548,218.074 h1.25
  text "G3" at 324.368,215.651 h1.25
  text "G3" at 374.068,215.651 h1.25
  text "Mid Layer 3" at 331.368,215.542 h1.25
  text "GERBER FILE" at 271.548,215.494 h1.25
  text "Board Layer 6" at 353.6,215.5 h1.25
  text "GP2" at 324.341,213.171 h1.25
  text "GP2" at 374.041,213.171 h1.25
  text "Board Layer 5" at 353.768,213.142 h1.25
  text "VCC" at 331.3,213.1 h1.25
  text "GERBER FILE" at 271.548,212.954 h1.25
  text "V-GROOVE" at 124.9,212.9 h1.25 r90
  text "V-GROOVE" at 134.9,212.9 h1.25 r90
  text "G4" at 324.3,210.6 h1.25
  text "Board Layer 7" at 353.6,210.6 h1.25
  text "G4" at 374,210.6 h1.25
  text "Mid Layer 4" at 331.368,210.542 h1.25
  text "GERBER FILE" at 271.548,210.414 h1.25
  text "BOTTOM LAYER" at 331.159,205.481 h1.25
  text "Board Layer 8" at 353.5,205.5 h1.25
  text "GBL" at 324.16,205.407 h1.25
  text "GBL" at 373.78,205.405 h1.25
  text "GERBER FILE" at 271.548,205.394 h1.25
  text "GBS" at 324.16,203.007 h1.25
  text "Bottom Solder Mask" at 331.159,202.992 h1.25
  text "GBS" at 373.78,202.865 h1.25
  text "GERBER FILE" at 271.548,202.854 h1.25
  text "GBO" at 324.16,200.407 h1.25
  text "Bottom Overlay" at 331.159,200.401 h1.25
  text "GBO" at 373.78,200.325 h1.25
  text "GERBER FILE" at 271.548,200.314 h1.25
  text "GBP" at 373.78,197.912 h1.25
  text "Bottom Paste Mask" at 331.159,197.861 h1.25
  text "GBP" at 324.16,197.811 h1.25
  text "GERBER FILE" at 271.548,197.774 h1.25
  text "APERTURE LIST" at 271.548,192.747 h1.25
  text "APR" at 324.161,192.671 h1.25
  text "DRILL REPORT" at 271.548,190.207 h1.25
  text "DRR" at 324.161,190.131 h1.25
  text "DRILL FILE" at 271.282,187.6 h1.25
  text "DRL" at 324.036,187.456 h1.25
  text "V-GROOVE" at -29.9,186.1 h1.25
  text "TXT" at 323.882,185.05 h1.25
  text "EXCELLON DRILL" at 271.207,184.975 h1.25
  text "MATERIAL:" at 271.802,179.77 h1.25
  text "GLASS FIBRE EPOXY RESIN NEMA GRADE FR4-08 (IPC-4101) - WITH TG170" at 297.456,179.516 h1.25
  text "X" at 294.789,179.389 h1.25
  text "THICKNESS:" at 279.676,176.595 h1.25
  text "0.8mm" at 297.456,176.595 h1.25
  text "1.2mm" at 315.109,176.595 h1.25
  text "1.6mm" at 332.762,176.595 h1.25
  text "2.4mm" at 350.542,176.595 h1.25
  text "3.2mm" at 368.322,176.595 h1.25
  text "X" at 330.349,176.468 h1.25
  text "2" at 326.5,173.7 h1.25
  text "TOLERANCE:" at 279.549,173.547 h1.25
  text "OTHER +/-" at 350.542,173.547 h1.25
  text "X" at 294.789,173.42 h1.25
  text "IN A/W IPC-D-300G CLASS" at 298.002,173.347 h1.25
  text "2" at 326.5,170.6 h1.25
  text "BOW & TWIST:" at 279.536,170.499 h1.25
  text "AS SHOWN" at 350.669,170.372 h1.25
  text "IN A/W IPC-D-300G CLASS" at 298.002,170.299 h1.25
  text "X" at 294.789,170.245 h1.25
  text "COPPER THICKNESS (FINISHED)" at 277.1,167.5 h1.25
  text "18um" at 297.456,164.911 h1.25
  text "35um" at 324.507,164.911 h1.25
  text "70um" at 350.796,164.911 h1.25
  text "OUTER:" at 280.7,164.8 h1.25
  text "X" at 321.764,164.708 h1.25
  text "18um" at 297.456,161.863 h1.25
  text "35um" at 324.507,161.863 h1.25
  text "70um" at 350.796,161.863 h1.25
  text "INNER SIGNAL:" at 277.2,161.8 h1.25
  text "X" at 294.7,161.7 h1.25
  text "INNER PWR:" at 280.7,158.8 h1.25
  text "18um" at 297.456,158.815 h1.25
  text "35um" at 324.507,158.815 h1.25
  text "70um" at 350.796,158.815 h1.25
  text "X" at 294.8,158.7 h1.25
  text "STRUCTURE:" at 271.802,155.767 h1.25
  text "REFER" at 297.456,155.767 h1.25
  text "AS PER DRAWING No." at 297.329,152.592 h1.25
  text "AS SHOWN" at 350.669,152.592 h1.25
  text "X" at 348.129,152.465 h1.25
  text "DRILLING:" at 271.802,149.798 h1.25
  text "COMPONENT SIDE" at 297.456,147.512 h1.25
  text "SOLDER SIDE" at 324.253,147.512 h1.25
  text "VIEWED FROM:" at 278.8,147.3 h1.25
  text "X" at 294.789,147.258 h1.25
  text "REFERENCE:" at 279.041,144.464 h1.25
  text "AS SHOWN" at 297.329,144.337 h1.25
  text "PATTERN MASTER LIST" at 324.38,144.337 h1.25
  text "X" at 348.129,144.337 h1.25
  text "NC_DRILL FILES" at 350.669,144.337 h1.25
  text "X" at 294.789,144.21 h1.25
  text "20um" at 324.507,141.416 h1.25
  text "PTH MINIMUM COPPER THICKNESS:" at 279.1,141.3 h1.25
  text "X" at 321.84,141.289 h1.25
  text "OTHER" at 350.669,141.289 h1.25
  text "NPTH:" at 279,138.4 h1.25
  text "TENTED" at 297.329,138.241 h1.25
  text "X" at 321.84,138.241 h1.25
  text "PADS REMOVED" at 324.38,138.241 h1.25
  text "REMOVE PADS" at 350.669,138.241 h1.25
  text "X" at 294.789,138.114 h1.25
  text "2nd DRILL" at 297.329,135.193 h1.25
  text "BOTH" at 324.38,135.193 h1.25
  text "AS SHOWN" at 336.699,135.193 h1.25
  text "NONE" at 350.669,135.193 h1.25
  text "BOARD FINISH:" at 271.802,132.272 h1.25
  text "X" at 294.789,132.145 h1.25
  text "ETCHING" at 297.329,132.145 h1.25
  text "REFER PATTERN MASTER LIST" at 324.38,132.145 h1.25
  text "NONE" at 305.802,129.208 h1.25
  text "LEGEND / SCREEN PRINT:" at 278.2,129.2 h1.25
  text "COMPONENT" at 324.377,129.173 h1.25
  text "SOLDER" at 350.702,129.108 h1.25
  text "X" at 321.837,129.046 h1.25
  text "X" at 348.162,128.981 h1.25
  text "WHITE" at 297.402,126.308 h1.25
  text "COLOUR:" at 284.1,126.2 h1.25
  text "X" at 294.862,126.181 h1.25
  text "YELLOW" at 324.38,126.049 h1.25
  text "OTHER" at 350.669,126.049 h1.25
  text "SOLDER RESIST:" at 278,123 h1.25
  text "X" at 294.789,123.001 h1.25
  text "LIQUID PHOTOIMAGEABLE" at 297.329,123.001 h1.25
  text "SCREEN PRINT" at 336.699,123.001 h1.25
  text "FINISH:" at 284.4,120 h1.25
  text "MATTE" at 297.329,119.953 h1.25
  text "GLOSS" at 310.029,119.953 h1.25
  text "X" at 307.362,119.826 h1.25
  text "COLOUR:" at 284.1,117 h1.25
  text "BLACK" at 297.329,116.905 h1.25
  text "GREEN" at 310.029,116.905 h1.25
  text "YELLOW" at 324.38,116.905 h1.25
  text "BLUE" at 336.699,116.905 h1.25
  text "OTHER" at 350.669,116.905 h1.25
  text "X" at 294.662,116.778 h1.25
  text "TRACK FINISH:" at 271.802,113.984 h1.25
  text "SELECTIVE SOLDER (HASL)" at 297.329,113.857 h1.25
  text "REFLOW SOLDER" at 336.699,113.857 h1.25
  text "0.1um - 0.2um ELECTROLESS GOLD OVER 3um NICKEL" at 297.4,111 h1.25
  text "X" at 294.8,110.9 h1.25
  text "IMMERSION GOLD" at 297.329,107.761 h1.25
  text "OTHER" at 336.699,107.761 h1.25
  text "EDGE BOARD" at 271.802,104.84 h1.25
  text "1.3um HARD GOLD OVER 5um     NICKEL / TIN-NICKEL" at 297.329,104.713 h1.25
  text "V-GROOVE" at -30.1,103.6 h1.25
  text "CONTACTS:" at 271.802,102.681 h1.25
  text "HARD FINISH GOLDE PLATE" at 297.329,101.665 h1.25
  text "OTHER" at 336.699,101.665 h1.25
  text "AS SHOWN" at 297.329,98.617 h1.25
  text "REFER" at 336.699,98.617 h1.25
  text "PROFILING:" at 271.802,95.569 h1.25
  text "AS DIMENSIONED, MEASURED AND CUT FROM SPECIFIED DATUM." at 297.329,95.569 h1.25
  text "X" at 294.789,95.442 h1.25
  text "V-GROOVE" at -29.9,93.8 h1.25
  text "REFER PCB BLANK DWG No." at 297.456,92.648 h1.25
  text "USE PROFILE / ROUTE TAPE SUPPLIED (REFER PATTERN MASTER LIST)" at 297.456,89.6 h1.25
  text "X" at 330.2,86.6 h1.25
  text "SQUARE CUT" at 297.456,86.552 h1.25
  text "N.C. ROUTE" at 315.236,86.552 h1.25
  text "V. SCORE" at 333.016,86.552 h1.25
  text "BLANK" at 350.796,86.552 h1.25
  text "ACCEPTABILITY:" at 271.802,83.885 h1.25
  text "MATERIALS AND WORKMANSHIP FOR ALL PRINTED WIRING BOARDS TO MEET" at 294.027,83.758 h1.25
  text "OR EXCEED THE REQUIREMENTS OF:" at 294.027,80.964 h1.25
  text "IPC-6011/12 AND IPC-A-600E" at 297.583,78.297 h1.25
  text "1" at 333.143,78.297 h1.25
  text "2" at 342.033,78.297 h1.25
  text "3" at 350.929,78.235 h1.25
  text "X" at 339.366,78.17 h1.25
  text "X" at 294.916,78.043 h1.25
  text "UL CERTIFICATION" at 297.583,75.249 h1.25
  text "AUSTEL" at 333.143,75.249 h1.25
  text "X" at 294.916,75.122 h1.25
  text "ML-P-55110F GRP" at 297.075,72.201 h1.25
  text "A" at 315.363,72.201 h1.25
  text "B" at 324.253,72.201 h1.25
  text "AS2546" at 333.143,72.201 h1.25
  text "OTHER" at 350.923,72.201 h1.25
  text "ADDITIONAL REQUIREMENTS:" at 271.6,68.9 h1.25
  text "NONE" at 297.549,66.322 h1.25
  text "SAMPLE PLAN" at 315.329,66.322 h1.25
  text "MIL-P-55110E SERIAL Nos. PER ORDER" at 335.109,66.322 h1.25
  text "X" at 294.85,66.307 h1.25
  text "MICROSECTION:" at 276.8,66.2 h1.25
  text "NONE" at 297.644,63.134 h1.25
  text "CERTIFICATION:" at 276.7,63 h1.25
  text "A" at 335.063,62.901 h1.25
  text "MIL-P-55110E GRP" at 315.219,62.851 h1.25
  text "B" at 340.429,62.822 h1.25
  text "1" at 365.129,62.722 h1.25
  text "2" at 370.495,62.643 h1.25
  text "3" at 375.995,62.643 h1.25
  text "IPC CLASS:" at 350.719,62.551 h1.25
  text "RoHS Compliant" at 297.644,59.934 h1.25
  text "X" at 294.85,59.807 h1.25
  text "X" at 312.588,59.718 h1.25
  text "QUALITY RELEASE REPORT" at 315.219,59.651 h1.25
  text "OTHER" at 350.823,59.601 h1.25
  text "NONE" at 297.589,56.722 h1.25
  text "REQUIRED (100% PADS & NETS)" at 315.369,56.722 h1.25
  text "PER ORDER" at 351.029,56.622 h1.25
  text "ELECTRICAL TEST:" at 276.7,56.6 h1.25
  text "X" at 312.702,56.595 h1.25
  text "NONE" at 297.589,53.522 h1.25
  text "1 SIDE" at 315.242,53.522 h1.25
  text "2 SIDES" at 334.745,53.535 h1.25
  text "MIN. PITCH" at 350.829,53.535 h1.25
  text "0.6mm" at 364.418,53.535 h1.25
  text "SURFACE MOUNT:" at 276.6,53.4 h1.25
  text "X" at 332.51,53.332 h1.25
  text "FOIL" at 335.149,50.382 h1.25
  text "Bottom Overlay" at 364.006,50.296 h1.25
  text "NONE" at 315.369,50.282 h1.25
  text "LEGEND" at 343.879,50.282 h1.25
  text "REFER" at 355.882,50.282 h1.25
  text "X" at 341.188,50.243 h1.25
  text "X" at 353.188,50.243 h1.25
  text "MANUFACTURER'S ID/LOGO:" at 276.6,50 h1.25
  text "NONE" at 335.2,47.2 h1.25
  text "ISO9001/AS3901" at 315.389,47.022 h1.25
  text "MANUFACTURER'S ACCREDITATION:" at 276.6,46.9 h1.25
  text "X" at 312.722,46.895 h1.25
  text "PACKAGING AND HANDLING:" at 276.6,44.1 h1.25
  text "REFER" at 335.149,43.886 h1.25
  text "PER ORDER" at 315.369,43.786 h1.25
  text "X" at 312.702,43.532 h1.25
  text "Notes" at 269,36.1 h1.25
  text "1. All dimensions are in mm." at 270.67,30.27 h1.25
  text "2. Controlled impedance traces are on TOP, MID1, MID2, MID3," at 270.3,23.6 h1.25
  text "MID4 and BOTTOM layers are 50 ohm single-ended, which is" at 274.3,18.6 h1.25
  text "achieved with 5 mil traces (on all layers)." at 274.3,13.6 h1.25
  text "V-GROOVE" at -29.7,11.6 h1.25
  text "3. Details for V-grooves and break off." at 270.6,5.8 h1.25
  text "0.07" at 310.282,-0.316 h1.25 r90
  text "+" at 309.774,-2.602 h1.25 r90
  text "-" at 311.044,-2.602 h1.25 r90
  text "0.40" at 310.282,-9.206 h1.25 r90
  text "Panel boundary coincides with centre-lines of tracks" at 0,-31.7 h1.25
  text ".Printout_Name" at 88.5,-31.7 h1.25
  text "0.1 MAX. DEVIATION" at 295.931,-33.971 h1.25
  text "Dimensions in millimetres" at 0.1,-35.7 h1.25

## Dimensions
246.4,8.3 to 133.2,-0.3 on 6. FabNotes
0,12.2 to -0.2,94.4 on 6. FabNotes
0,104.4 to -0.2,186.6 on 6. FabNotes
0,94.4 to -0.2,104.4 on 6. FabNotes
0,186.6 to 0,198.8 on 6. FabNotes
0,0 to 0,198.8 on 6. FabNotes
123.2,2.4 to 133.2,2.4 on 6. FabNotes
10,1.6 to 0,11.6 on 6. FabNotes
256.4,2.3 to 246.4,12.3 on 6. FabNotes
0,0 to 0,12.2 on 6. FabNotes
0,0 to 256.4,0 on 6. FabNotes
123.2,8.3 to 10,-0.3 on 6. FabNotes

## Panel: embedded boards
"DB32.PcbDoc" at 246.4,12.2, 2 rows x 2 columns, spacing 123.2 x 92.2, rotation 90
